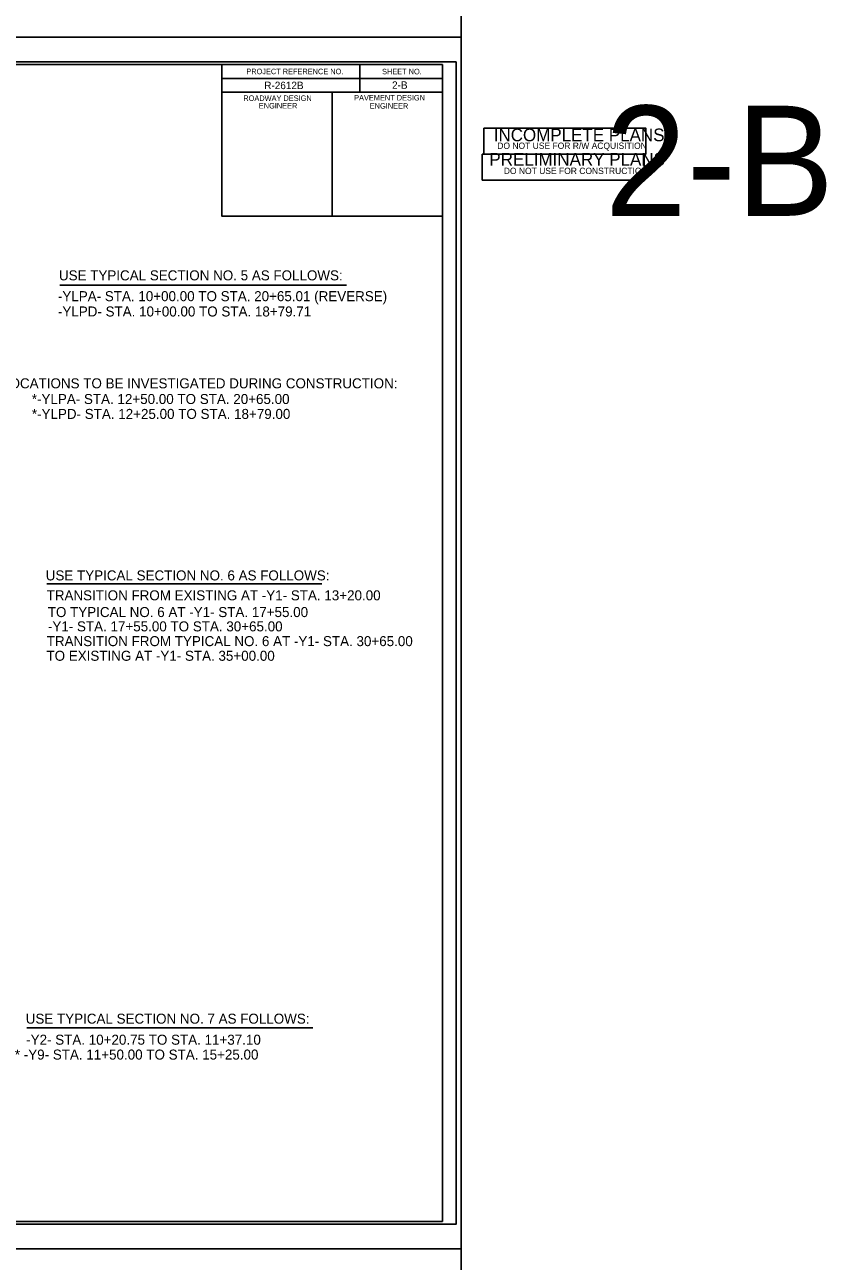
# Model space of a CAD drawing. Extents: x 573813 to 575363, y -54752 to -53123.
# Drawn here: x 574927.5 to 575073, y -53785.4 to -53560.8 of the extents above; entities that cross this region are included whole.
import ezdxf

# ---------------------------------------------------------------- set-up
doc = ezdxf.new("R2010")
doc.units = 0
for name, color, linetype in [('Old_Level_1', 7, 'Continuous'), ('Old_Level_11', 7, 'Continuous'), ('Sheet Cutting Line CELL', 7, 'Continuous'), ('Sheet Data Field CELL', 7, 'Continuous'), ('Sheet Plot Border Inside CELL', 7, 'Continuous'), ('Sheet Plot Border Outside CELL', 7, 'Continuous'), ('Sheet Sticker Incomplete CELL', 7, 'Continuous'), ('Sheet Sticker Preliminary CELL', 7, 'Continuous'), ('Sheet Typical CELL', 7, 'Continuous')]:
    doc.layers.add(name, color=color, linetype=linetype)

msp = doc.modelspace()

# ---------------------------------------------------------------- linework, layer by layer
at = {"layer": 'Old_Level_11'}
for p, q in [((574933.85, -53608.12), (574985.9, -53608.12)), ((574931.53, -53662.41), (574981.42, -53662.41)), ((574927.89, -53743.01), (574979.82, -53743.01))]:
    msp.add_line(p, q, dxfattribs=at)
at = {"layer": 'Sheet Cutting Line CELL'}
for p, q in [((575006.71, -53563.07), (574669.73, -53563.07)), ((574669.73, -53563.07), (575006.71, -53563.07)), ((575006.71, -53783.19), (574669.73, -53783.19)), ((574669.73, -53783.19), (575006.71, -53783.19))]:
    msp.add_line(p, q, dxfattribs=at)
at = {"layer": 'Sheet Plot Border Inside CELL'}
msp.add_lwpolyline([(575005.81, -53567.56), (574672.33, -53567.56), (574672.33, -53778.7), (575005.81, -53778.7)], close=True, dxfattribs=at)
at = {"layer": 'Sheet Plot Border Outside CELL'}
for p, q in [((575006.71, -53563.07), (575006.71, -53342.95)), ((574669.73, -53563.07), (575006.71, -53563.07)), ((575006.71, -53563.07), (574669.73, -53563.07)), ((575006.71, -53783.19), (575006.71, -53563.07)), ((574669.73, -53783.19), (575006.71, -53783.19)), ((575006.71, -53783.19), (574669.73, -53783.19)), ((575006.71, -54003.31), (575006.71, -53783.19))]:
    msp.add_line(p, q, dxfattribs=at)
for points in [[(575006.71, -53342.95), (574669.73, -53342.95), (574669.73, -53563.07), (575006.71, -53563.07)], [(575006.71, -53563.07), (574669.73, -53563.07), (574669.73, -53783.19), (575006.71, -53783.19)], [(575006.71, -53783.19), (574669.73, -53783.19), (574669.73, -54003.31), (575006.71, -54003.31)]]:
    msp.add_lwpolyline(points, close=True, dxfattribs=at)
at = {"layer": 'Sheet Sticker Incomplete CELL'}
msp.add_lwpolyline([(575010.84, -53584.33), (575010.84, -53579.63), (575040.26, -53579.63), (575040.26, -53584.33)], close=True, dxfattribs=at)
at = {"layer": 'Sheet Sticker Preliminary CELL'}
msp.add_lwpolyline([(575010.54, -53589.04), (575010.54, -53584.34), (575039.96, -53584.34), (575039.96, -53589.04)], close=True, dxfattribs=at)
at = {"layer": 'Sheet Typical CELL'}
for p, q in [((574988.3, -53568.08), (574988.3, -53573.09)), ((574963.28, -53570.58), (575003.31, -53570.58)), ((574983.3, -53573.09), (574983.3, -53595.59))]:
    msp.add_line(p, q, dxfattribs=at)
for points in [[(575003.31, -53568.07), (574703.15, -53568.07), (574703.15, -53778.19), (575003.31, -53778.19)], [(574963.28, -53568.07), (575003.31, -53568.07), (575003.31, -53573.09), (574963.28, -53573.09)], [(574963.28, -53573.09), (574983.3, -53573.09), (574983.3, -53595.6), (574963.28, -53595.6)], [(574983.3, -53573.09), (575003.31, -53573.09), (575003.31, -53595.6), (574983.3, -53595.6)]]:
    msp.add_lwpolyline(points, close=True, dxfattribs=at)

# ---------------------------------------------------------------- texts
at = {"layer": 'Old_Level_1'}
for s, rotation, p in [('USE TYPICAL SECTION NO. 5 AS FOLLOWS:', 360, (574933.71, -53607.26)), ('-YLPA- STA. 10+00.00 TO STA. 20+65.01 (REVERSE)', 0, (574933.52, -53611.04)), ('-YLPD- STA. 10+00.00 TO STA. 18+79.71', 0, (574933.52, -53613.82)), ('THESE LOCATIONS TO BE INVESTIGATED DURING CONSTRUCTION:', 360, (574914.6, -53626.87)), ('*-YLPA- STA. 12+50.00 TO STA. 20+65.00', 0, (574928.78, -53629.72)), ('*-YLPD- STA. 12+25.00 TO STA. 18+79.00', 0, (574928.79, -53632.43)), ('USE TYPICAL SECTION NO. 6 AS FOLLOWS:', 360, (574931.31, -53661.76)), ('TRANSITION FROM EXISTING AT -Y1- STA. 13+20.00', 0, (574931.47, -53665.38)), ('TO TYPICAL NO. 6 AT -Y1- STA. 17+55.00', 0, (574931.68, -53668.42)), ('-Y1- STA. 17+55.00 TO STA. 30+65.00', 0, (574931.71, -53671.02)), ('TRANSITION FROM TYPICAL NO. 6 AT -Y1- STA. 30+65.00', 360, (574931.49, -53673.7)), ('TO EXISTING AT -Y1- STA. 35+00.00', 360, (574931.44, -53676.36)), ('USE TYPICAL SECTION NO. 7 AS FOLLOWS:', 360, (574927.68, -53742.28)), ('-Y2- STA. 10+20.75 TO STA. 11+37.10', 0, (574927.76, -53746.1)), ('* -Y9- STA. 11+50.00 TO STA. 15+25.00', 0, (574925.7, -53748.8))]:
    msp.add_text(s, height=1.8192, rotation=rotation, dxfattribs=at).set_placement(p)
at = {"layer": 'Sheet Data Field CELL'}
for s, height, p in [('R-2612B  ', 1.351, (574970.98, -53572.52)), ('2-B', 1.351, (574994.18, -53572.46)), ('2-B', 20, (575032.79, -53595.54))]:
    msp.add_text(s, height=height, dxfattribs=at).set_placement(p)
at = {"layer": 'Sheet Sticker Incomplete CELL'}
for s, height, p in [('INCOMPLETE PLANS', 2.3052, (575012.63, -53581.99)), ('DO NOT USE FOR R/W ACQUISITION', 1.1526, (575013.28, -53583.38))]:
    msp.add_text(s, height=height, dxfattribs=at).set_placement(p)
at = {"layer": 'Sheet Sticker Preliminary CELL'}
for s, height, p in [('PRELIMINARY PLANS', 2.3052, (575011.84, -53586.41)), ('DO NOT USE FOR CONSTRUCTION', 1.1526, (575014.46, -53587.95))]:
    msp.add_text(s, height=height, dxfattribs=at).set_placement(p)
at = {"layer": 'Sheet Typical CELL'}
for s, height, p in [('PROJECT REFERENCE NO.', 1.0006, (574967.72, -53569.81)), ('SHEET NO.', 1.001, (574992.36, -53569.83)), ('ROADWAY DESIGN', 1.0006, (574967.18, -53574.67)), ('PAVEMENT DESIGN', 1.0006, (574987.29, -53574.58)), ('ENGINEER', 1.001, (574969.99, -53576.04)), ('ENGINEER', 1.001, (574990.13, -53576.07))]:
    msp.add_text(s, height=height, dxfattribs=at).set_placement(p)

doc.saveas('drawing.dxf')
